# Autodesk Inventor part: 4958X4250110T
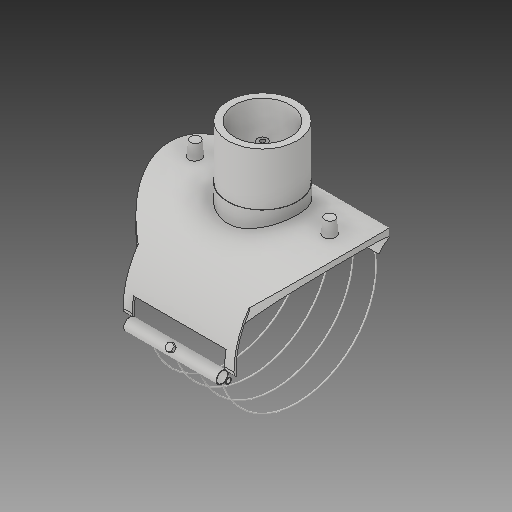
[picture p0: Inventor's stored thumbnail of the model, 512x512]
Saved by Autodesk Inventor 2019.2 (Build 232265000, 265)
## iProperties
Created: 2020-06
Part Number: 4958X4250110T
Material: Generic
Description: Plasson Branch Saddle 250x110
Document SubType Name: Modeling
Designer: KIM
Density: 1 g/cm^3
Appearance: Default
Author: KIM
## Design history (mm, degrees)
derived "4958X4.ipt"
feature "Solid1::4958X4.ipt"
tag "TaggingFeature1"
body "Solid1"
other parameters: "d0" = 295, "d3" = 268, "d4" = 111, "d7" = 89, "d9" = 84, "d10" = 0.5, "d11" = 1, "d12" = 27.75, "d13" = 16, "d14" = 8, "d16" = 10 deg, "d17" = 10 deg, "d19" = 0, "d23" = 0, "d26" = 0, "d27" = 177, "d28" = 0, "d29" = 147.5, "d30" = 0, "d31" = 1, "d32" = 1, "d33" = 19.2, "d34" = 9.6, "d35" = 45 deg, "d36" = 147.5, "d37" = 0, "d38" = 5, "d39" = 85 deg, "d40" = 27.75, "d41" = 16, "d42" = 107.27273, "d49" = 3, "d50" = 6, "d51" = 5, "d54" = 0, "d57" = 35 deg, "d60" = 18.4375, "d61" = 1, "d62" = 90 deg, "d63" = 2, "d64" = 0, "d65" = 0, "d68" = 36.875, "d70" = 0.57711, "d71" = 10 deg, "d73" = 3.15, "L" = 295, "LS" = 84, "H1" = 111, "Dt" = 16, "di" = 89, "d72" = 9
